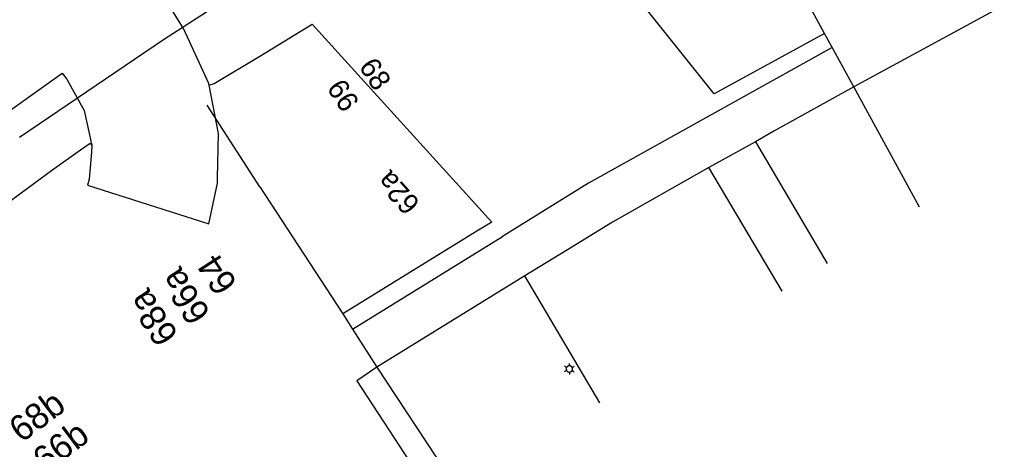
# Model space of a CAD drawing. Extents: x 81065 to 81486, y 452384 to 452681.
# Drawn here: x 81179.58 to 81217.68, y 452426.85 to 452443.54 of the extents above; entities that cross this region are included whole.
import ezdxf

# ---------------------------------------------------------------- set-up
doc = ezdxf.new("R2010")
doc.units = 0
for name, color, linetype in [('B-BH-AL-TOPOGRAFIE_HUISNUMMER-T25', 7, 'Continuous'), ('B-BH-GR-GROENVOORZIENING-GV', 7, 'Continuous'), ('B-BH-IE-MEUBILAIR_WEGMEUBILAIR_LICHTMAST-S', 7, 'Continuous'), ('B-BH-OG-TOPOGRAFIE_BEBOUWING-GV', 7, 'Continuous'), ('B-BH-OG-TOPOGRAFIE_BEBOUWING_PANDSCHEIDING-GV', 7, 'Continuous'), ('B-BH-VH-KANTOPSLUITING-GV', 7, 'Continuous')]:
    doc.layers.add(name, color=color, linetype=linetype)

msp = doc.modelspace()

# ---------------------------------------------------------------- linework, layer by layer
at = {"layer": 'B-BH-GR-GROENVOORZIENING-GV'}
msp.add_line((81214.503, 452436.263), (81211.96, 452440.929), dxfattribs=at)
at = {"layer": 'B-BH-IE-MEUBILAIR_WEGMEUBILAIR_LICHTMAST-S'}
for p, q in [((81200.809, 452430.036), (81200.73, 452430.082)), ((81200.809, 452429.914), (81200.73, 452429.868)), ((81200.915, 452430.097), (81200.915, 452430.189)), ((81201.02, 452430.036), (81201.1, 452430.082)), ((81201.02, 452429.914), (81201.1, 452429.868)), ((81200.915, 452429.853), (81200.915, 452429.761))]:
    msp.add_line(p, q, dxfattribs=at)
msp.add_lwpolyline([(81200.793, 452429.975), (81200.794, 452429.962), (81200.795, 452429.949), (81200.799, 452429.937), (81200.803, 452429.925), (81200.809, 452429.914), (81200.816, 452429.903), (81200.824, 452429.893), (81200.833, 452429.884), (81200.843, 452429.876), (81200.854, 452429.869), (81200.865, 452429.863), (81200.877, 452429.859), (81200.89, 452429.855), (81200.902, 452429.854), (81200.915, 452429.853), (81200.928, 452429.854), (81200.94, 452429.855), (81200.953, 452429.859), (81200.965, 452429.863), (81200.976, 452429.869), (81200.987, 452429.876), (81200.997, 452429.884), (81201.006, 452429.893), (81201.014, 452429.903), (81201.021, 452429.914), (81201.026, 452429.925), (81201.031, 452429.937), (81201.034, 452429.949), (81201.036, 452429.962), (81201.037, 452429.975), (81201.036, 452429.988), (81201.034, 452430), (81201.031, 452430.013), (81201.026, 452430.025), (81201.021, 452430.036), (81201.014, 452430.047), (81201.006, 452430.057), (81200.997, 452430.066), (81200.987, 452430.074), (81200.976, 452430.081), (81200.965, 452430.086), (81200.953, 452430.091), (81200.94, 452430.094), (81200.928, 452430.096), (81200.915, 452430.097), (81200.902, 452430.096), (81200.889, 452430.094), (81200.877, 452430.091), (81200.865, 452430.086), (81200.854, 452430.081), (81200.843, 452430.074), (81200.833, 452430.066), (81200.824, 452430.057), (81200.816, 452430.047), (81200.809, 452430.036), (81200.803, 452430.025), (81200.799, 452430.013), (81200.795, 452430), (81200.794, 452429.988), (81200.793, 452429.975)], dxfattribs=at)
at = {"layer": 'B-BH-OG-TOPOGRAFIE_BEBOUWING-GV'}
msp.add_line((81192.118, 452432.111), (81192.498, 452431.52), dxfattribs=at)
for points in [[(81211.96, 452440.929), (81210.814, 452443.005), (81206.534, 452440.655), (81200.066, 452448.769), (81205.913, 452452.053), (81205.606, 452452.621), (81235.506, 452468.904), (81238.146, 452470.28), (81239.352, 452467.994), (81239.739, 452468.204)], [(81244.855, 452458.824), (81211.96, 452440.929)], [(81204.716, 452454.266), (81195.963, 452449.411), (81187.411, 452444.21), (81185.162, 452442.763)], [(81186.938, 452440.997), (81187.133, 452441.059), (81188.903, 452442.118), (81190.938, 452443.364), (81197.901, 452435.681), (81197.321, 452435.323)], [(81185.162, 452442.763), (81179.582, 452438.967)], [(81211.114, 452442.462), (81201.663, 452437.191), (81198.314, 452435.119)], [(81187.264, 452437.389), (81187.298, 452439.113), (81186.938, 452440.997)], [(81181.948, 452438.481), (81182.319, 452438.743), (81182.387, 452438.657)], [(81182.387, 452438.657), (81182.389, 452438.643), (81182.368, 452438.395)], [(81153.251, 452396.796), (81151.969, 452398.03), (81148.503, 452394.479), (81139.858, 452400.091), (81144.562, 452405.184), (81143.704, 452406.025), (81150.532, 452412.867), (81157.636, 452419.422), (81158.509, 452420.19), (81166.091, 452426.576), (81171.032, 452430.467), (81180.823, 452437.684), (81181.948, 452438.481)], [(81182.365, 452438.395), (81182.277, 452437.341), (81182.215, 452437.115), (81186.918, 452435.608), (81187.26, 452437.195), (81187.264, 452437.389)], [(81197.321, 452435.323), (81192.118, 452432.111)], [(81192.498, 452431.52), (81198.314, 452435.119)], [(81192.498, 452431.52), (81193.447, 452430.048), (81192.664, 452429.509), (81195.76, 452424.77)]]:
    msp.add_lwpolyline(points, dxfattribs=at)
at = {"layer": 'B-BH-OG-TOPOGRAFIE_BEBOUWING_PANDSCHEIDING-GV'}
for p, q in [((81210.814, 452443.005), (81205.913, 452452.053)), ((81186.845, 452440.214), (81188.896, 452437.053)), ((81188.902, 452437.052), (81192.118, 452432.111))]:
    msp.add_line(p, q, dxfattribs=at)
at = {"layer": 'B-BH-VH-KANTOPSLUITING-GV'}
for p, q in [((81208.134, 452438.802), (81206.321, 452437.797)), ((81199.193, 452433.586), (81193.447, 452430.048)), ((81202.099, 452428.657), (81199.193, 452433.586)), ((81193.447, 452430.048), (81196.586, 452425.276))]:
    msp.add_line(p, q, dxfattribs=at)
for points in [[(81186.938, 452440.997), (81186.918, 452441.056), (81185.937, 452443.2), (81185.347, 452444.153), (81191.344, 452447.929), (81190.629, 452449.149), (81194.948, 452451.753), (81202.427, 452455.953), (81205.999, 452457.801), (81206.662, 452456.613), (81223.822, 452465.932), (81237.064, 452473.144), (81239.739, 452468.204)], [(81178.135, 452439.264), (81181.23, 452441.459), (81181.418, 452441.226), (81182.089, 452440.012), (81182.387, 452438.657)], [(81211.96, 452440.929), (81208.844, 452439.204), (81208.134, 452438.802)], [(81208.134, 452438.802), (81210.922, 452434.066)], [(81206.321, 452437.797), (81202.588, 452435.675), (81200.841, 452434.6)], [(81209.172, 452432.993), (81206.321, 452437.797)], [(81200.841, 452434.6), (81199.193, 452433.586)]]:
    msp.add_lwpolyline(points, dxfattribs=at)

# ---------------------------------------------------------------- texts
at = {"layer": 'B-BH-AL-TOPOGRAFIE_HUISNUMMER-T25'}
for s, height, rotation, p in [('68', 0.8, 302.9824, (81192.724, 452441.718)), ('66', 0.8, 302.9824, (81191.477, 452440.885)), ('62a', 0.8, 132.0482, (81195.162, 452436.424)), ('64', 1, 122.9774, (81188.064, 452433.286)), ('66a', 1, 122.9774, (81187.024, 452432.132)), ('68a', 1, 122.9774, (81185.779, 452431.296)), ('68b', 1, 36.9, (81179.657, 452427.083)), ('66b', 1, 36.9, (81180.577, 452425.898))]:
    msp.add_text(s, height=height, rotation=rotation, dxfattribs=at).set_placement(p)

doc.saveas('drawing.dxf')
